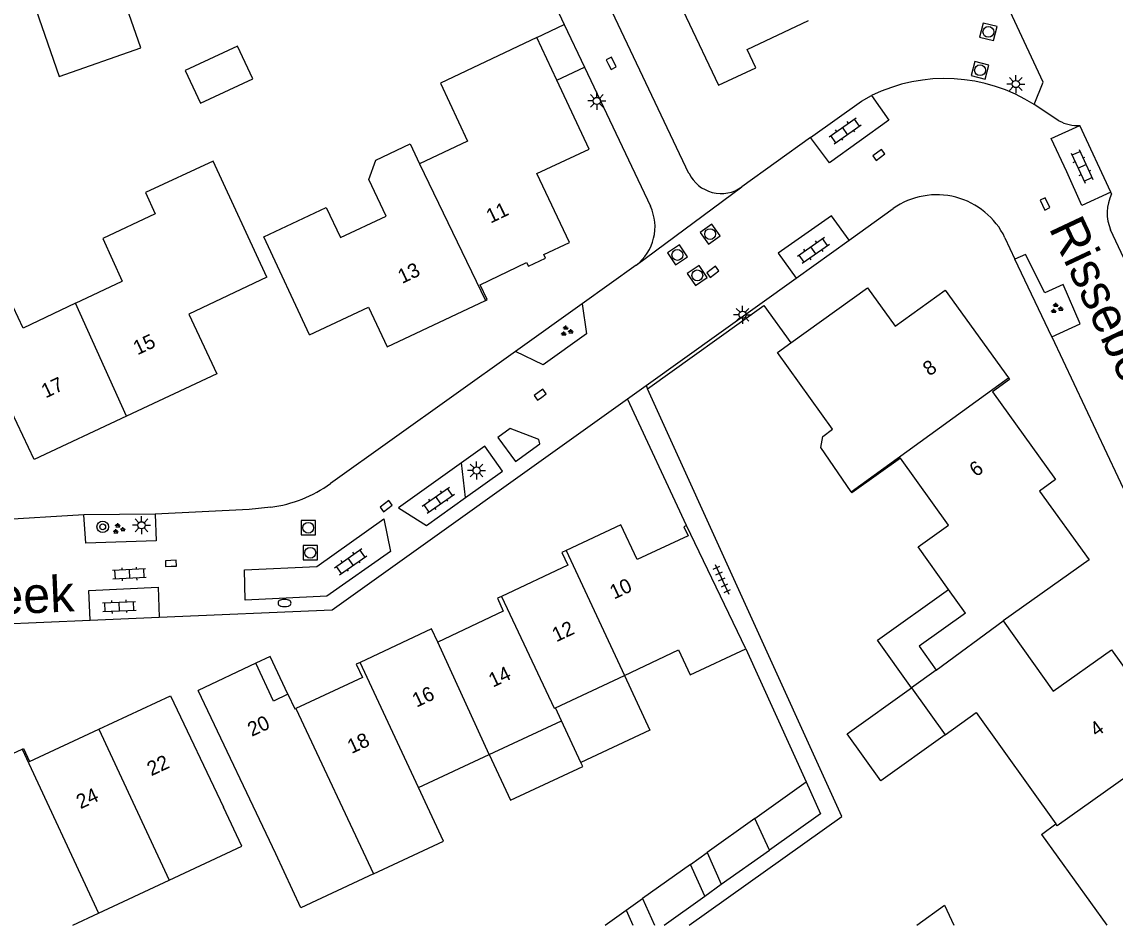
# Model space of a CAD drawing. Extents: x 128999 to 131010, y 395498 to 399007.
# Drawn here: x 130874.7 to 130950.5, y 395500 to 395562.6 of the extents above; entities that cross this region are included whole.
import ezdxf

# ---------------------------------------------------------------- set-up
doc = ezdxf.new("R2010")
doc.units = 0
for name, color, linetype in [('gg-afsc-erfafscheiding', 7, 'Continuous'), ('gg-afsc-muur', 7, 'Continuous'), ('gg-anno-huisnummerreeks BGT', 7, 'Continuous'), ('gg-anno-openbare ruimte label', 7, 'Continuous'), ('gg-bbg-bijgebouw', 7, 'Continuous'), ('gg-bbg-gedigitaliseerde bebouwing', 7, 'Continuous'), ('gg-bbg-gedigitaliseerde bijgebouw', 7, 'Continuous'), ('gg-bbg-hoofdgebouw', 7, 'Continuous'), ('gg-bbg-luifel en loopbrug', 7, 'Continuous'), ('gg-bbg-onder overbouw', 7, 'Continuous'), ('gg-bbg-pand overbouw', 7, 'Continuous'), ('gg-bbg-tussenscheiding', 7, 'Continuous'), ('gg-knt-verharding', 7, 'Continuous'), ('gg-knt-verharding nz', 7, 'Continuous'), ('gt-grn-vlakafsluiter', 7, 'Continuous'), ('gt-grn-weggrens', 7, 'Continuous'), ('gt-symb-boom', 7, 'Continuous'), ('gt-symb-brandkraan', 7, 'Continuous'), ('gt-symb-groenvak', 7, 'Continuous'), ('gt-symb-klinker verharding', 7, 'Continuous'), ('gt-symb-kolk', 7, 'Continuous'), ('gt-symb-lichtmast', 7, 'Continuous'), ('gt-symb-rioolschacht', 7, 'Continuous'), ('gt-symb-tegel verharding', 7, 'Continuous')]:
    doc.layers.add(name, color=color, linetype=linetype)

# ---------------------------------------------------------------- blocks, each defined once
blk = doc.blocks.new('gt0-RS')
at = {"layer": 'gt-symb-rioolschacht'}
blk.add_lwpolyline([(-0.5, -0.5), (0.5, -0.5), (0.5, 0.5), (-0.5, 0.5)], close=True, dxfattribs=at)
blk.add_circle((0, 0), 0.375, dxfattribs=at)
blk = doc.blocks.new('gt0-GRVAK')
at = {"layer": 'gt-symb-groenvak'}
for p, q in [((-0.11, 0.189), (-0.228, 0.24)), ((-0.182, 0.153), (0.088, 0.153)), ((-0.091, 0.211), (-0.156, 0.322)), ((-0.047, 0.214), (-0.047, 0.393)), ((-0.004, 0.211), (0.061, 0.322)), ((0.015, 0.189), (0.133, 0.24)), ((0.262, -0.052), (0.197, 0.059)), ((0.305, -0.049), (0.305, 0.13)), ((0.349, -0.052), (0.414, 0.059)), ((-0.245, -0.228), (-0.363, -0.177)), ((-0.318, -0.264), (-0.047, -0.264)), ((-0.226, -0.206), (-0.291, -0.095)), ((-0.183, -0.203), (-0.183, -0.024)), ((-0.139, -0.206), (-0.074, -0.095)), ((-0.12, -0.228), (-0.002, -0.177)), ((0.243, -0.074), (0.125, -0.023)), ((0.17, -0.11), (0.441, -0.11)), ((0.368, -0.074), (0.486, -0.023))]:
    blk.add_line(p, q, dxfattribs=at)
blk = doc.blocks.new('gt0-LMAST')
at = {"layer": 'gt-symb-lichtmast'}
for p, q in [((-0.182, 0.173), (-0.447, 0.438)), ((-0.005, 0.246), (-0.005, 0.621)), ((0.172, 0.173), (0.437, 0.438)), ((-0.255, -0.004), (-0.63, -0.004)), ((-0.182, -0.181), (-0.447, -0.446)), ((-0.005, -0.254), (-0.005, -0.629)), ((0.437, -0.446), (0.172, -0.181)), ((0.245, -0.004), (0.62, -0.004))]:
    blk.add_line(p, q, dxfattribs=at)
blk.add_circle((-0.005, -0.004), 0.25, dxfattribs=at)
blk = doc.blocks.new('gt0-KOLK')
at = {"layer": 'gt-symb-kolk'}
blk.add_lwpolyline([(0, 0), (0.375, 0), (0.375, 0.4), (-0.375, 0.4), (-0.375, 0), (0, 0)], dxfattribs=at)
blk = doc.blocks.new('gt0-KL1')
at = {"layer": 'gt-symb-klinker verharding'}
for p, q in [((-1.15, 0.3), (1.15, 0.3)), ((-1, -0.3), (-1, 0.3)), ((-0.5, 0.3), (-0.5, 0.45)), ((0, -0.3), (0, 0.3)), ((0.5, 0.3), (0.5, 0.45)), ((1, -0.3), (1, 0.3)), ((-1.15, -0.3), (1.15, -0.3)), ((-0.5, -0.45), (-0.5, -0.3)), ((0.5, -0.45), (0.5, -0.3))]:
    blk.add_line(p, q, dxfattribs=at)
blk = doc.blocks.new('gt0-BOOM')
at = {"layer": 'gt-symb-boom'}
for radius in [0.4, 0.2]:
    blk.add_circle((0, 0), radius, dxfattribs=at)
blk = doc.blocks.new('gt0-TEG1')
at = {"layer": 'gt-symb-tegel verharding'}
for p, q in [((-1.125, 0), (1.125, 0)), ((-0.9, -0.25), (-0.9, 0.25)), ((-0.45, -0.25), (-0.45, 0.25)), ((0, -0.25), (0, 0.25)), ((0.45, -0.25), (0.45, 0.25)), ((0.9, -0.25), (0.9, 0.25))]:
    blk.add_line(p, q, dxfattribs=at)
blk = doc.blocks.new('gt0-BR')
at = {"layer": 'gt-symb-brandkraan'}
for centre, radius, start, end in [((-0.244, 0), 0.206, 107.56694, 252.43307), ((0.599, -2.664), 3, 106.89205, 107.56694), ((0, -0.691), 0.938, 73.10799, 106.89205), ((-0.599, -2.664), 3, 72.43309, 73.10799), ((0.244, 0), 0.206, 287.56695, 72.43309), ((0.599, 2.664), 3, 252.43307, 253.10797), ((0, 0.691), 0.938, 253.10797, 286.89206), ((-0.599, 2.664), 3, 286.89206, 287.56695)]:
    blk.add_arc(centre, radius, start, end, dxfattribs=at)

msp = doc.modelspace()

# ---------------------------------------------------------------- linework, layer by layer
at = {"layer": 'gg-afsc-erfafscheiding'}
for p, q in [((130917.979, 395537.433), (130918.091, 395537.187)), ((130920.788, 395527.721), (130916.687, 395536.509)), ((130924.89, 395519.16), (130929.079, 395509.938))]:
    msp.add_line(p, q, dxfattribs=at)
msp.add_lwpolyline([(130920.981, 395500), (130931.558, 395507.542), (130918.091, 395537.187)], dxfattribs=at)
at = {"layer": 'gg-afsc-muur'}
msp.add_lwpolyline([(130918.091, 395537.187), (130926.146, 395542.976), (130928.014, 395540.378)], dxfattribs=at)
at = {"layer": 'gg-bbg-bijgebouw'}
msp.add_lwpolyline([(130875.49, 395564.059), (130877.295, 395558.864), (130882.963, 395560.833), (130881.158, 395566.028), (130875.49, 395564.059)], dxfattribs=at)
at = {"layer": 'gg-bbg-gedigitaliseerde bebouwing'}
for p, q in [((130910.418, 395561.57), (130903.722, 395558.386)), ((130924.89, 395519.16), (130920.788, 395527.721)), ((130940.133, 395521.647), (130938.959, 395523.286)), ((130911.7, 395515.08), (130916.478, 395517.324)), ((130938.097, 395517.682), (130936.39, 395516.46)), ((130892.31, 395504.94), (130886.934, 395516.279)), ((130936.39, 395516.46), (130938.73, 395513.2)), ((130885.011, 395515.907), (130888.69, 395508.19)), ((130912.12, 395514.18), (130911.7, 395515.08)), ((130907.101, 395511.839), (130912.12, 395514.18)), ((130902.199, 395509.552), (130907.101, 395511.839)), ((130945.411, 395506.293), (130946.39, 395507.02)), ((130880.022, 395500.836), (130884.916, 395503.119)), ((130878.231, 395500), (130880.022, 395500.836))]:
    msp.add_line(p, q, dxfattribs=at)
for points in [[(130903.722, 395558.386), (130905.61, 395554.38), (130902.27, 395552.81)], [(130896.8, 395547.69), (130899.965, 395549.177), (130898.761, 395551.721), (130899.237, 395553.051), (130901.622, 395554.18), (130902.27, 395552.81)], [(130891.688, 395544.929), (130887.96, 395552.98), (130883.274, 395550.802), (130883.954, 395549.322), (130880.31, 395547.62), (130881.663, 395544.656)], [(130894.645, 395540.951), (130891.48, 395547.74), (130895.81, 395549.78), (130896.8, 395547.69)], [(130938.959, 395523.286), (130936.85, 395526.23), (130938.96, 395527.74), (130935.628, 395532.393), (130932.255, 395529.977)], [(130940.133, 395521.647), (130936.91, 395519.339), (130938.097, 395517.682)], [(130916.478, 395517.324), (130920.24, 395519.09), (130921.05, 395517.36), (130924.89, 395519.16)], [(130938.73, 395513.2), (130940.88, 395514.74), (130946.39, 395507.02)], [(130899.082, 395503.556), (130903.939, 395505.823), (130902.199, 395509.552)], [(130884.916, 395503.119), (130889.958, 395505.472), (130888.69, 395508.19)], [(130899.082, 395503.556), (130894.051, 395501.209), (130892.31, 395504.94)]]:
    msp.add_lwpolyline(points, dxfattribs=at)
at = {"layer": 'gg-bbg-gedigitaliseerde bijgebouw'}
for p, q in [((130925.52, 395507.4), (130922.21, 395505.04)), ((130926.53, 395505.21), (130925.52, 395507.4)), ((130922.21, 395505.04), (130923.19, 395502.84)), ((130923.19, 395502.84), (130926.53, 395505.21)), ((130921.06, 395504.21), (130917.74, 395501.85)), ((130922.06, 395502.01), (130921.06, 395504.21)), ((130917.74, 395501.85), (130918.577, 395500)), ((130919.243, 395500), (130922.06, 395502.01)), ((130915.157, 395500), (130916.6, 395501.03)), ((130916.6, 395501.03), (130917.066, 395500))]:
    msp.add_line(p, q, dxfattribs=at)
msp.add_lwpolyline([(130886.027, 395559.272), (130887.078, 395557.004), (130890.707, 395558.685), (130889.657, 395560.953), (130886.027, 395559.272)], dxfattribs=at)
at = {"layer": 'gg-bbg-hoofdgebouw'}
for p, q in [((130911.799, 395558.612), (130910.418, 395561.57)), ((130878.426, 395543.125), (130881.663, 395544.656)), ((130932.21, 395530.042), (130932.255, 395529.977)), ((130890.937, 395518.165), (130886.934, 395516.279)), ((130880.041, 395513.591), (130885.011, 395515.907)), ((130945.411, 395506.293), (130949.921, 395500))]:
    msp.add_line(p, q, dxfattribs=at)
for points in [[(130918.529, 395567.715), (130922.993, 395558.248), (130925.6, 395559.468), (130924.997, 395560.73), (130929.242, 395562.733)], [(130906.856, 395543.332), (130906.967, 395543.384), (130906.472, 395544.415), (130909.7, 395545.966), (130909.825, 395545.706), (130911.011, 395546.253), (130910.9, 395546.505), (130912.664, 395547.342), (130910.412, 395552.132), (130914.034, 395553.822), (130911.799, 395558.612)], [(130878.426, 395543.125), (130874.798, 395541.409), (130872.697, 395545.852), (130866.861, 395543.104), (130867.033, 395542.739)], [(130891.688, 395544.929), (130886.274, 395542.367), (130888.22, 395538.231), (130881.96, 395535.292)], [(130928.014, 395540.378), (130933.336, 395544.203), (130935.252, 395541.537), (130938.725, 395544.034), (130943.101, 395537.946)], [(130894.645, 395540.951), (130898.726, 395542.869), (130900.034, 395540.104), (130906.856, 395543.332)], [(130932.21, 395530.042), (130930.091, 395533.123), (130930.227, 395533.88), (130930.916, 395534.395), (130927.103, 395539.723), (130928.014, 395540.378)], [(130943.101, 395537.946), (130943.172, 395537.848), (130941.995, 395536.986), (130946.364, 395530.9), (130945.262, 395530.106), (130948.697, 395525.345), (130942.742, 395521.102)], [(130881.96, 395535.292), (130875.553, 395532.283), (130873.586, 395536.463)], [(130920.788, 395527.721), (130920.604, 395527.635), (130920.896, 395527.01), (130917.364, 395525.358), (130916.237, 395527.767), (130912.436, 395525.986)], [(130912.436, 395525.986), (130912.141, 395525.848), (130912.558, 395524.954), (130907.953, 395522.801)], [(130907.953, 395522.801), (130907.671, 395522.669), (130908.072, 395521.785), (130903.539, 395519.633)], [(130942.742, 395521.102), (130946.22, 395516.221), (130950.255, 395519.096), (130954.788, 395512.786)], [(130903.539, 395519.633), (130903.115, 395520.543), (130898.166, 395518.221)], [(130898.166, 395518.221), (130897.89, 395518.092), (130898.323, 395517.185), (130893.705, 395515.03)], [(130893.15, 395516.014), (130893.633, 395514.996), (130893.705, 395515.03)], [(130868.212, 395513.358), (130868.317, 395513.407), (130869.917, 395509.99), (130874.719, 395512.204)], [(130874.719, 395512.204), (130874.819, 395512.25), (130875.233, 395511.351), (130880.041, 395513.591)]]:
    msp.add_lwpolyline(points, dxfattribs=at)
at = {"layer": 'gg-bbg-luifel en loopbrug'}
for p, q in [((130910.418, 395561.57), (130912.314, 395562.455)), ((130912.314, 395562.455), (130913.712, 395559.505)), ((130911.799, 395558.612), (130913.712, 395559.505)), ((130913.469, 395511.287), (130912.12, 395514.18)), ((130925.52, 395507.4), (130929.079, 395509.938)), ((130921.06, 395504.21), (130922.21, 395505.04)), ((130922.06, 395502.01), (130923.19, 395502.84)), ((130916.6, 395501.03), (130917.74, 395501.85))]:
    msp.add_line(p, q, dxfattribs=at)
for points in [[(130936.39, 395516.46), (130934.03, 395519.757), (130938.959, 395523.286)], [(130916.478, 395517.324), (130918.253, 395513.518), (130913.469, 395511.287)], [(130938.73, 395513.2), (130934.258, 395509.997), (130931.921, 395513.259), (130936.39, 395516.46)], [(130907.101, 395511.839), (130908.58, 395508.667), (130913.599, 395511.008), (130913.469, 395511.287)], [(130929.079, 395509.938), (130930.082, 395507.73), (130926.53, 395505.21)], [(130936.748, 395500), (130938.668, 395501.384), (130939.322, 395500)]]:
    msp.add_lwpolyline(points, dxfattribs=at)
at = {"layer": 'gg-bbg-onder overbouw'}
msp.add_lwpolyline([(130893.15, 395516.014), (130892.154, 395515.544), (130890.937, 395518.165)], dxfattribs=at)
at = {"layer": 'gg-bbg-pand overbouw'}
msp.add_lwpolyline([(130893.15, 395516.014), (130891.923, 395518.63), (130890.937, 395518.165)], dxfattribs=at)
at = {"layer": 'gg-bbg-tussenscheiding'}
for p, q in [((130902.27, 395552.81), (130906.856, 395543.332)), ((130881.96, 395535.292), (130878.426, 395543.125)), ((130932.21, 395530.042), (130943.101, 395537.946)), ((130912.436, 395525.986), (130916.478, 395517.324)), ((130938.097, 395517.682), (130942.742, 395521.102)), ((130907.101, 395511.839), (130903.539, 395519.633)), ((130902.199, 395509.552), (130898.166, 395518.221)), ((130893.705, 395515.03), (130899.082, 395503.556)), ((130880.041, 395513.591), (130884.916, 395503.119)), ((130874.719, 395512.204), (130880.022, 395500.836))]:
    msp.add_line(p, q, dxfattribs=at)
for points in [[(130907.953, 395522.801), (130911.615, 395515.04), (130911.7, 395515.08)], [(130954.788, 395512.786), (130946.485, 395506.886), (130946.39, 395507.02)]]:
    msp.add_lwpolyline(points, dxfattribs=at)
at = {"layer": 'gg-knt-verharding'}
for p, q in [((130909.95, 395567.446), (130912.314, 395562.455)), ((130913.712, 395559.505), (130918.283, 395549.857)), ((130946.61, 395555.785), (130944.899, 395556.909)), ((130950.206, 395550.824), (130948.066, 395555.465)), ((130929.377, 395554.615), (130924.629, 395551.199)), ((130950.26, 395550.707), (130950.206, 395550.824)), ((130932.054, 395547.5), (130935.119, 395549.692)), ((130954.756, 395538.453), (130950.193, 395548.212)), ((130928.389, 395544.878), (130932.054, 395547.5)), ((130942.865, 395547.677), (130943.561, 395546.196)), ((130946.106, 395540.798), (130943.561, 395546.196)), ((130917.291, 395545.761), (130913.548, 395543.085)), ((130917.979, 395537.433), (130928.389, 395544.878)), ((130913.548, 395543.085), (130908.918, 395539.779)), ((130946.106, 395540.798), (130957.087, 395517.486)), ((130908.918, 395539.779), (130896.097, 395530.623)), ((130916.687, 395536.509), (130917.979, 395537.433)), ((130883.957, 395528.498), (130879.008, 395528.449)), ((130842.922, 395519.552), (130879.44, 395521.143)), ((130879.44, 395521.143), (130884.213, 395521.351))]:
    msp.add_line(p, q, dxfattribs=at)
for points in [[(130920.959, 395552.14), (130908.172, 395579.106), (130904.867, 395577.918)], [(130929.377, 395554.615), (130932.909, 395557.156), (130933.606, 395557.529)], [(130946.106, 395540.798), (130948.082, 395541.714), (130946.899, 395544.421), (130945.626, 395543.861), (130944.287, 395546.514), (130943.561, 395546.196)], [(130913.548, 395543.085), (130913.855, 395541.014), (130910.859, 395538.855), (130908.918, 395539.779)], [(130884.213, 395521.351), (130896.227, 395521.874), (130916.687, 395536.509)], [(130879.008, 395528.449), (130872.908, 395528.095), (130872.656, 395528.09), (130872.401, 395528.106)], [(130883.957, 395528.498), (130884.012, 395526.647), (130879.148, 395526.494), (130879.008, 395528.449)], [(130891.976, 395528.981), (130890.474, 395528.824), (130883.957, 395528.498)]]:
    msp.add_lwpolyline(points, dxfattribs=at)
for centre, radius, start, end in [((130938.701, 395547.165), 11.548, 57.53834, 116.17675), ((130947.897, 395558.169), 2.709, 241.63416, 273.57502), ((130923.19, 395553.215), 2.476, 205.71624, 305.52173), ((130938.141, 395545.414), 5.238, 25.60034, 125.23682), ((130952.935, 395549.387), 2.983, 153.72981, 203.19372), ((130915.241, 395548.426), 3.362, 307.56933, 25.20231), ((130890.691, 395538.199), 9.308, 277.93833, 305.511)]:
    msp.add_arc(centre, radius, start, end, dxfattribs=at)
at = {"layer": 'gg-knt-verharding nz'}
msp.add_line((130905.462, 395529.657), (130905.196, 395532.069), dxfattribs=at)
for points in [[(130933.606, 395557.529), (130934.815, 395555.834), (130930.694, 395552.857), (130929.377, 395554.615)], [(130950.206, 395550.824), (130948.199, 395549.898), (130947.165, 395552.244), (130946.062, 395554.564), (130948.066, 395555.465)], [(130932.054, 395547.5), (130930.846, 395549.201), (130927.15, 395546.596), (130928.389, 395544.878)], [(130905.196, 395532.069), (130900.825, 395528.946), (130902.755, 395527.725), (130905.462, 395529.657)], [(130890.185, 395522.532), (130890.136, 395524.64), (130895.166, 395524.877), (130899.791, 395528.179), (130900.263, 395525.911), (130895.848, 395522.804), (130890.185, 395522.532)], [(130879.44, 395521.143), (130879.337, 395523.211), (130884.147, 395523.436), (130884.213, 395521.351)]]:
    msp.add_lwpolyline(points, dxfattribs=at)
at = {"layer": 'gt-grn-vlakafsluiter'}
msp.add_lwpolyline([(130944.899, 395556.909), (130945.521, 395558.453), (130936.687, 395577.395), (130932.858, 395585.373)], dxfattribs=at)
at = {"layer": 'gt-grn-weggrens'}
msp.add_line((130917.291, 395545.761), (130924.629, 395551.199), dxfattribs=at)
for points in [[(130908.924, 395532.16), (130910.628, 395533.371), (130910.552, 395533.692), (130908.559, 395534.45), (130907.704, 395533.814), (130908.924, 395532.16)], [(130905.462, 395529.657), (130908.036, 395531.494), (130906.799, 395533.214), (130905.196, 395532.069)]]:
    msp.add_lwpolyline(points, dxfattribs=at)

# ---------------------------------------------------------------- block references
at = {"layer": 'gt-symb-boom'}
msp.add_blockref('gt0-BOOM', (130880.308, 395527.621), dxfattribs=at)
at = {"layer": 'gt-symb-brandkraan'}
msp.add_blockref('gt0-BR', (130892.915, 395522.337), dxfattribs=at)
at = {"layer": 'gt-symb-groenvak'}
for p in [(130946.439, 395542.766), (130912.46, 395541.194), (130881.409, 395527.481)]:
    msp.add_blockref('gt0-GRVAK', p, dxfattribs=at)
at = {"layer": 'gt-symb-klinker verharding'}
for p, rotation in [((130931.782, 395555.086), 35.23135738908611), ((130948.212, 395552.628), -65.48492926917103), ((130929.583, 395546.807), 35.231357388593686), ((130903.58, 395529.472), 35.23135738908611), ((130897.5, 395525.202), 35.23135738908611), ((130882.149, 395524.356), -177.47809205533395), ((130881.459, 395522.098), 2.7508347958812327)]:
    msp.add_blockref('gt0-KL1', p, dxfattribs=dict(at, rotation=rotation))
at = {"layer": 'gt-symb-kolk'}
for p, rotation in [((130915.387, 395559.679), -63.639941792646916), ((130934.233, 395553.26), 36.53738634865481), ((130945.461, 395549.932), -64.79277878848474), ((130922.731, 395545.149), 36.5373863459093), ((130910.765, 395536.627), 36.5373863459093), ((130900.083, 395528.894), 36.53738634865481), ((130885.045, 395524.89), 2.407413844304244)]:
    msp.add_blockref('gt0-KOLK', p, dxfattribs=dict(at, rotation=rotation))
at = {"layer": 'gt-symb-lichtmast'}
for p in [(130943.62, 395558.338), (130914.572, 395557.165), (130924.681, 395542.339), (130906.238, 395531.54), (130883.004, 395527.734)]:
    msp.add_blockref('gt0-LMAST', p, dxfattribs=at)
at = {"layer": 'gt-symb-rioolschacht'}
for p, rotation in [((130941.715, 395561.952), -13.952823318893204), ((130941.14, 395559.29), -14.244742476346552), ((130922.425, 395547.926), 36.01052539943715), ((130920.154, 395546.48), -146.21457204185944), ((130921.536, 395545.064), -146.1669713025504)]:
    msp.add_blockref('gt0-RS', p, dxfattribs=dict(at, rotation=rotation))
for p in [(130894.56, 395527.559), (130894.7, 395525.827)]:
    msp.add_blockref('gt0-RS', p, dxfattribs=at)
at = {"layer": 'gt-symb-tegel verharding', "rotation": -64.97272120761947}
msp.add_blockref('gt0-TEG1', (130923.24, 395523.982), dxfattribs=at)

# ---------------------------------------------------------------- texts
at = {"layer": 'gg-anno-huisnummerreeks BGT'}
for s, rotation, p in [('11', 25.7, (130907.2, 395548.647)), ('13', 25.3, (130901.066, 395544.464)), ('15', 25.2, (130882.718, 395539.513)), ('8', 35.7, (130937.629, 395538.04)), ('17', 25.2, (130876.348, 395536.522)), ('6', 35.7, (130940.857, 395531.047)), ('10', 25.1, (130915.755, 395522.572)), ('12', 25.1, (130911.756, 395519.611)), ('14', 25.4, (130907.362, 395516.466)), ('16', 25.2, (130902.064, 395515.077)), ('20', 25.2, (130890.644, 395513.053)), ('4', 35.7, (130949.216, 395513.022)), ('18', 25, (130897.562, 395511.864)), ('22', 25, (130883.676, 395510.321)), ('24', 25, (130878.768, 395508.034))]:
    msp.add_text(s, height=1, rotation=rotation, dxfattribs=at).set_placement(p)
at = {"layer": 'gg-anno-openbare ruimte label'}
for rotation, p in [(295.2, (130945.876, 395548.36)), (2.5, (130862.78, 395521.084))]:
    msp.add_text('Rissebeek', height=2.5, rotation=rotation, dxfattribs=at).set_placement(p)

doc.saveas('drawing.dxf')
